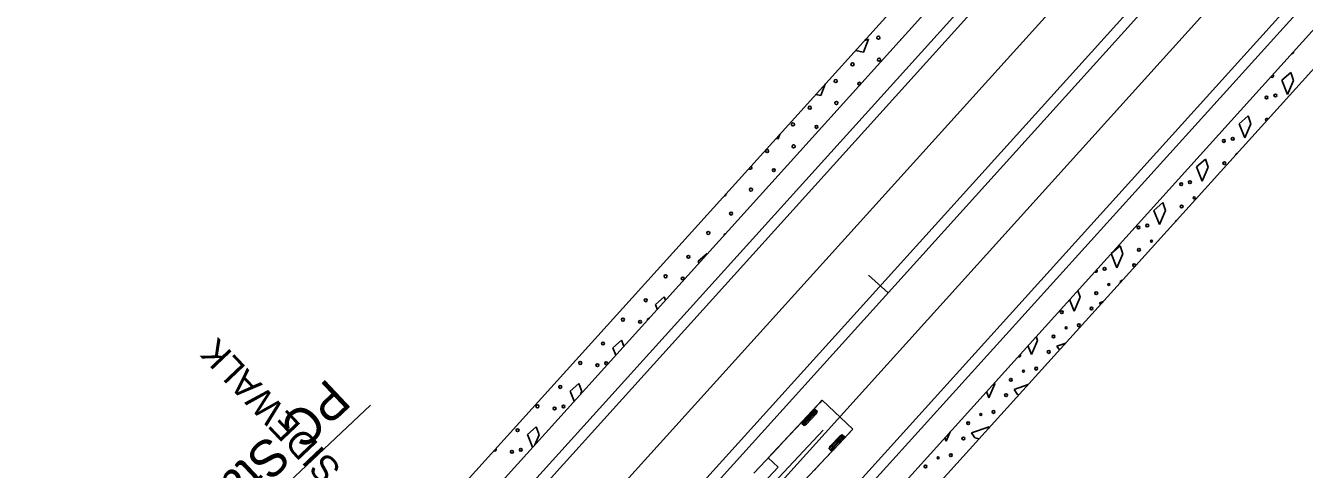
# Model space of a CAD drawing. Extents: x 1262642 to 1268358, y 767825 to 773481.
# Drawn here: x 1266795.4 to 1267038.7, y 772328.8 to 772413.2 of the extents above; entities that cross this region are included whole.
import ezdxf

# ---------------------------------------------------------------- set-up
doc = ezdxf.new("R2010")
doc.units = 0
for name, color, linetype in [('Prop Conc 2ft 6in Curb and Gutter', 7, 'Continuous'), ('Prop Conc 4in Sidewalk', 7, 'Continuous'), ('Prop Dimension Text', 7, 'Continuous'), ('Prop EOT', 7, 'Continuous'), ('Prop Horizontal Alignment', 7, 'Continuous'), ('Prop Horizontal Alignment Station Label', 7, 'Continuous'), ('Prop Horizontal Alignment Tick Small', 7, 'Continuous'), ('Prop Lane Lines', 7, 'Continuous'), ('Scratch_Level_3', 7, 'Continuous')]:
    doc.layers.add(name, color=color, linetype=linetype)

msp = doc.modelspace()

# ---------------------------------------------------------------- linework, layer by layer
at = {"layer": 'Prop Conc 2ft 6in Curb and Gutter'}
for p, q in [((1267131.94, 772606.25), (1266835.45, 772278.08)), ((1267135.45, 772602.68), (1266839.16, 772274.72)), ((1267138.61, 772599.46), (1266842.5, 772271.71)), ((1267174.15, 772567.2), (1266880.18, 772241.82)), ((1266883.52, 772238.8), (1267177.49, 772564.18)), ((1267181.29, 772560.93), (1266887.23, 772235.45)), ((1266954.81, 772408.16), (1266955.73, 772410.66)), ((1266955.73, 772410.66), (1266955.02, 772410.42)), ((1266953.27, 772408.48), (1266954.81, 772408.16)), ((1267034.43, 772402.82), (1267036.12, 772404.31)), ((1267035.51, 772400.14), (1267034.43, 772402.82)), ((1267036.64, 772402.78), (1267035.51, 772400.14)), ((1267036.12, 772404.31), (1267036.64, 772402.78)), ((1266945.71, 772400.12), (1266946.69, 772399.92)), ((1266946.69, 772399.92), (1266947.48, 772402.08)), ((1267026.31, 772394.57), (1267027.99, 772396.07)), ((1267027.99, 772396.07), (1267028.52, 772394.53)), ((1267027.39, 772391.89), (1267026.31, 772394.57)), ((1267028.52, 772394.53), (1267027.39, 772391.89)), ((1266938.16, 772391.76), (1266938.56, 772391.67)), ((1266938.56, 772391.67), (1266938.9, 772392.57)), ((1267018.18, 772386.33), (1267019.87, 772387.82)), ((1267019.87, 772387.82), (1267020.39, 772386.29)), ((1267019.26, 772383.65), (1267018.18, 772386.33)), ((1267020.39, 772386.29), (1267019.26, 772383.65)), ((1267010.06, 772378.08), (1267011.75, 772379.58)), ((1267011.14, 772375.4), (1267010.06, 772378.08)), ((1267012.27, 772378.05), (1267011.14, 772375.4)), ((1267011.75, 772379.58), (1267012.27, 772378.05)), ((1267001.94, 772369.84), (1267003.62, 772371.34)), ((1267003.62, 772371.34), (1267004.15, 772369.8)), ((1266923.34, 772368.39), (1266925.03, 772369.88)), ((1266923.48, 772368.05), (1266923.34, 772368.39)), ((1266925.03, 772369.88), (1266925.06, 772369.8)), ((1267003.02, 772367.16), (1267001.94, 772369.84)), ((1267004.15, 772369.8), (1267003.02, 772367.16)), ((1266915.22, 772360.14), (1266916.9, 772361.64)), ((1266916.9, 772361.64), (1266917.12, 772361.01)), ((1266994.89, 772358.91), (1266994.01, 772361.1)), ((1266996.02, 772361.56), (1266994.89, 772358.91)), ((1266995.59, 772362.84), (1266996.02, 772361.56)), ((1266915.56, 772359.29), (1266915.22, 772360.14)), ((1267000.44, 772360.75), (1266999.72, 772360.51)), ((1266999.72, 772360.51), (1266999.93, 772360.19)), ((1266987.65, 772354.05), (1266987.9, 772353.31)), ((1266907.09, 772351.9), (1266908.78, 772353.4)), ((1266907.65, 772350.53), (1266907.09, 772351.9)), ((1266908.78, 772353.4), (1266909.18, 772352.23)), ((1266986.77, 772350.67), (1266986.1, 772352.34)), ((1266987.9, 772353.31), (1266986.77, 772350.67)), ((1266993.28, 772352.83), (1266991.6, 772352.26)), ((1266991.6, 772352.26), (1266992.09, 772351.51)), ((1266898.97, 772343.65), (1266900.66, 772345.15)), ((1266900.66, 772345.15), (1266901.18, 772343.62)), ((1266979.78, 772345.07), (1266978.65, 772342.43)), ((1266979.71, 772345.26), (1266979.78, 772345.07)), ((1266986.13, 772344.92), (1266983.48, 772344.02)), ((1266983.48, 772344.02), (1266984.12, 772343.03)), ((1266899.73, 772341.77), (1266898.97, 772343.65)), ((1266901.18, 772343.62), (1266900.98, 772343.15)), ((1266978.65, 772342.43), (1266978.18, 772343.58)), ((1266984.12, 772343.03), (1266984.38, 772342.98)), ((1266890.85, 772335.41), (1266892.53, 772336.91)), ((1266892.53, 772336.91), (1266893.06, 772335.37)), ((1266978.72, 772336.91), (1266975.35, 772335.77)), ((1266978.6, 772336.58), (1266978.72, 772336.91)), ((1266891.82, 772333.01), (1266890.85, 772335.41)), ((1266893.06, 772335.37), (1266892.25, 772333.49)), ((1266970.52, 772334.18), (1266970.27, 772334.81)), ((1266971.27, 772335.92), (1266970.52, 772334.18)), ((1266975.35, 772335.77), (1266976, 772334.79)), ((1266976, 772334.79), (1266976.83, 772334.62))]:
    msp.add_line(p, q, dxfattribs=at)
for centre, radius in [((1266957.63, 772410.93), 0.285), ((1266952.71, 772405.86), 0.292), ((1266957.75, 772406.75), 0.289), ((1266949.51, 772402.69), 0.285), ((1267033.17, 772399.93), 0.268), ((1266944.58, 772397.61), 0.292), ((1266949.63, 772398.51), 0.289), ((1267031.49, 772399.54), 0.268), ((1266941.38, 772394.44), 0.285), ((1266945.85, 772393.95), 0.268), ((1266941.5, 772390.26), 0.289), ((1267023.37, 772391.29), 0.268), ((1267025.05, 772391.68), 0.268), ((1266936.46, 772389.37), 0.292), ((1266937.73, 772385.71), 0.268), ((1267023.46, 772387.05), 0.268), ((1267015.25, 772383.05), 0.268), ((1267016.92, 772383.44), 0.268), ((1266933.38, 772382.02), 0.289), ((1267017.72, 772380.47), 0.18), ((1267015.34, 772378.81), 0.268), ((1266929.6, 772377.46), 0.268), ((1266925.26, 772373.78), 0.289), ((1267007.12, 772374.8), 0.268), ((1267008.8, 772375.19), 0.268), ((1267007.21, 772370.56), 0.268), ((1267009.6, 772372.23), 0.18), ((1266921.48, 772369.22), 0.268), ((1266917.13, 772365.53), 0.289), ((1267000.68, 772366.95), 0.268), ((1267006.29, 772367.63), 0.268), ((1266920.4, 772365.11), 0.268), ((1267001.48, 772363.98), 0.18), ((1266913.36, 772360.97), 0.268), ((1266999.09, 772362.32), 0.268), ((1266992.55, 772358.7), 0.268), ((1266998.17, 772359.39), 0.268), ((1266909.01, 772357.29), 0.289), ((1266912.28, 772356.86), 0.268), ((1266995.79, 772356.21), 0.268), ((1266990.97, 772354.08), 0.268), ((1266993.35, 772355.74), 0.18), ((1266905.23, 772352.73), 0.268), ((1266990.04, 772351.14), 0.268), ((1266900.89, 772349.04), 0.289), ((1266904.16, 772348.62), 0.268), ((1266905.83, 772349.01), 0.268), ((1266985.23, 772347.49), 0.18), ((1266987.67, 772347.96), 0.268), ((1266897.11, 772344.48), 0.268), ((1266982.84, 772345.83), 0.268), ((1266981.92, 772342.9), 0.268), ((1266892.76, 772340.8), 0.289), ((1266896.03, 772340.38), 0.268), ((1266897.71, 772340.76), 0.268), ((1266977.11, 772339.25), 0.18), ((1266979.54, 772339.72), 0.268), ((1266974.72, 772337.59), 0.268), ((1266888.99, 772336.24), 0.268), ((1266973.8, 772334.65), 0.268), ((1266887.91, 772332.13), 0.268), ((1266889.59, 772332.52), 0.268), ((1266971.42, 772331.48), 0.268), ((1266966.6, 772329.34), 0.268), ((1266968.99, 772331), 0.18)]:
    msp.add_circle(centre, radius, dxfattribs=at)
for centre, radius, start, end in [((1266962.1, 772410.44), 0.268, 110.6441, 165.1636), ((1267036.35, 772408.2), 0.289, 263.3992, 12.4085), ((1266953.97, 772402.19), 0.268, 330.3735, 305.4341), ((1267032.57, 772403.65), 0.268, 209.4151, 66.3926), ((1267031.58, 772395.3), 0.268, 37.0285, 238.7791), ((1267025.85, 772388.71), 0.18, 84.6805, 191.1271), ((1266933.26, 772386.2), 0.285, 208.9883, 66.8193), ((1266928.34, 772381.12), 0.292, 260.8915, 14.9161), ((1267014.41, 772375.88), 0.268, 107.0688, 168.7388), ((1266928.53, 772373.35), 0.268, 93.4563, 182.3514), ((1266999, 772366.56), 0.268, 219.7361, 56.0715), ((1267003.91, 772364.45), 0.268, 68.8587, 206.9489), ((1266913.96, 772357.25), 0.268, 88.1221, 187.6855), ((1266984.43, 772350.46), 0.268, 223.6669, 52.1407), ((1266884.64, 772332.55), 0.289, 232.3498, 43.4578)]:
    msp.add_arc(centre, radius, start, end, dxfattribs=at)
at = {"layer": 'Prop Conc 4in Sidewalk'}
for p, q in [((1267131.94, 772606.25), (1266835.45, 772278.08)), ((1267135.45, 772602.68), (1266839.16, 772274.72)), ((1267177.49, 772564.18), (1266883.52, 772238.8)), ((1267181.2, 772560.83), (1266887.23, 772235.45))]:
    msp.add_line(p, q, dxfattribs=at)
at = {"layer": 'Prop EOT'}
for p, q in [((1267140.02, 772598.03), (1266843.99, 772270.37)), ((1267172.67, 772568.54), (1266878.7, 772243.16))]:
    msp.add_line(p, q, dxfattribs=at)
at = {"layer": 'Prop Horizontal Alignment'}
msp.add_line((1266770.94, 772153.71), (1267443.05, 772897.65), dxfattribs=at)
at = {"layer": 'Prop Horizontal Alignment Station Label'}
msp.add_line((1266683.11, 772173.74), (1266861, 772340.98), dxfattribs=at)
at = {"layer": 'Prop Horizontal Alignment Tick Small'}
msp.add_line((1266959.48, 772362.4), (1266955.77, 772365.76), dxfattribs=at)
at = {"layer": 'Prop Lane Lines'}
for p, q in [((1267148.18, 772590.66), (1266852.15, 772262.99)), ((1267156.34, 772583.29), (1266860.31, 772255.62)), ((1267164.5, 772575.91), (1266868.47, 772248.25))]:
    msp.add_line(p, q, dxfattribs=at)
at = {"layer": 'Scratch_Level_3'}
for p, q in [((1266946.93, 772341.93), (1266936.68, 772330.98)), ((1266952.77, 772336.46), (1266946.93, 772341.93)), ((1266946.93, 772341.93), (1266946.93, 772341.93)), ((1266945.62, 772340.19), (1266943.11, 772337.51)), ((1266945.78, 772340.03), (1266943.28, 772337.36)), ((1266945.95, 772339.88), (1266943.44, 772337.2)), ((1266841.29, 772223.32), (1266947.12, 772336.27)), ((1266942.52, 772325.51), (1266952.77, 772336.46)), ((1266950.79, 772335.35), (1266948.28, 772332.67)), ((1266950.95, 772335.19), (1266948.45, 772332.51)), ((1266951.12, 772335.03), (1266948.61, 772332.36)), ((1266936.68, 772330.98), (1266938.55, 772329.23)), ((1266938.55, 772329.23), (1266931.32, 772321.5))]:
    msp.add_line(p, q, dxfattribs=at)
for points in [[(1266933.93, 772328.05), (1266935.07, 772329.27), (1266936.21, 772330.49), (1266937.35, 772331.7), (1266938.49, 772332.92), (1266939.63, 772334.14), (1266940.77, 772335.35), (1266941.91, 772336.57), (1266943.05, 772337.79), (1266944.19, 772339.01), (1266945.33, 772340.22), (1266946.47, 772341.44), (1266946.93, 772341.93)], [(1266945.47, 772328.67), (1266946.61, 772329.89), (1266947.75, 772331.1), (1266948.89, 772332.32), (1266950.03, 772333.54), (1266951.17, 772334.75), (1266952.31, 772335.97), (1266952.77, 772336.46)]]:
    msp.add_lwpolyline(points, dxfattribs=at)
for points in [[(1266945.58, 772340.23), (1266945.99, 772339.84), (1266945.77, 772339.34), (1266943.96, 772337.42), (1266943.49, 772337.16), (1266943.07, 772337.55), (1266943.29, 772338.05), (1266945.1, 772339.97)], [(1266950.75, 772335.39), (1266951.16, 772335), (1266950.94, 772334.5), (1266949.13, 772332.58), (1266948.66, 772332.32), (1266948.24, 772332.71), (1266948.46, 772333.2), (1266950.27, 772335.13)]]:
    msp.add_lwpolyline(points, close=True, dxfattribs=at)

# ---------------------------------------------------------------- texts
at = {"layer": 'Prop Dimension Text'}
msp.add_text("5' SIDEWALK", height=5, rotation=133.4955, dxfattribs=at).set_placement((1266860.36, 772324.05))
at = {"layer": 'Prop Horizontal Alignment Station Label'}
msp.add_text('PC Sta.  16+94.83', height=7, rotation=223.2333, dxfattribs=at).set_placement((1266852.87, 772346.32))

doc.saveas('drawing.dxf')
